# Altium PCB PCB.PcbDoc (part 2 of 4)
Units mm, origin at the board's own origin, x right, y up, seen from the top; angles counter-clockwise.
Board outline 430 x 130 mm, 2 copper layers (Top Layer, Bottom Layer); 471 components, 267 nets, 1806 pads, 471 vias.
Unrouted connection lines stored in the file: 127.
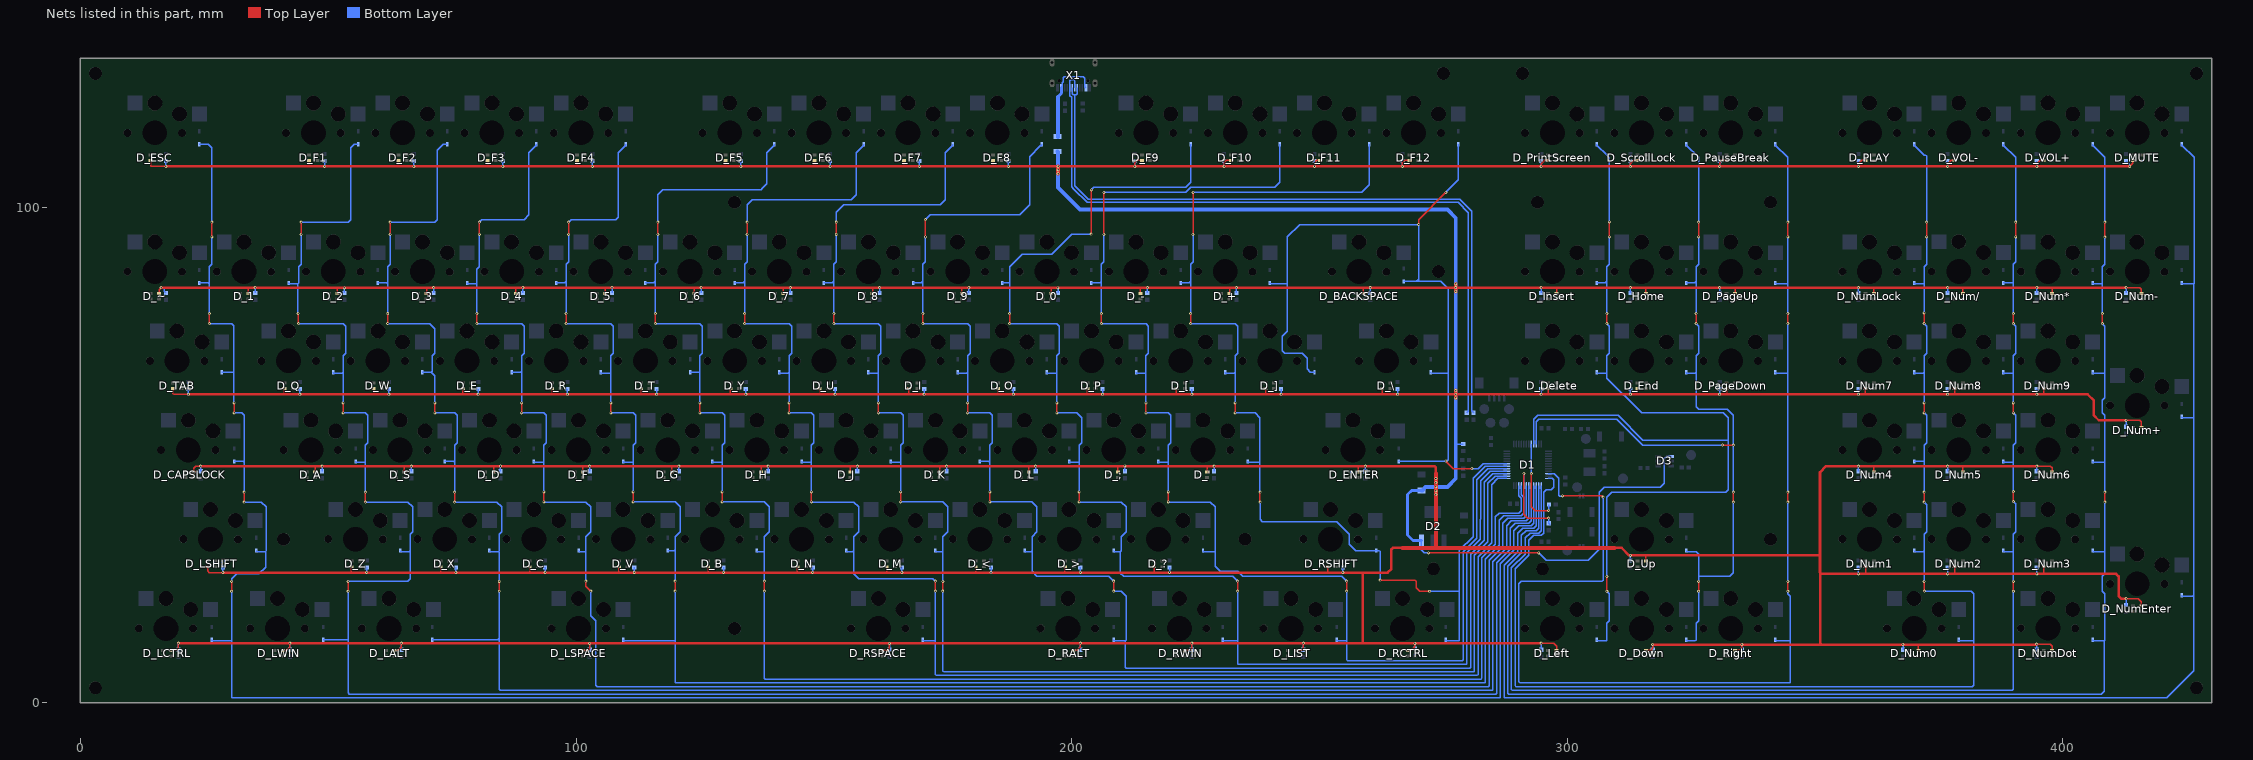
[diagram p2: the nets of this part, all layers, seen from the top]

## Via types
v1: diameter 0.6, hole 0.3, Top Layer to Bottom Layer, tented both sides, 471 vias

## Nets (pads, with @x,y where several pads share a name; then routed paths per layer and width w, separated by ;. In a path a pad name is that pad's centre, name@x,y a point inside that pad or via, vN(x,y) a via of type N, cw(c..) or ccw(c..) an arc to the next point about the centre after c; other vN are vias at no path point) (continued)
+5: C7.1 C9.2 C10.2 C11.2 C12.2 C13.2 C14.2 C15.2 C16.2 C17.2 C18.2 C19.2 C20.2 C21.2 C22.2 C23.2 C24.2 C25.2 C26.2 C27.2 C28.2 C29.2 C30.2 C31.2 C32.2 C33.2 C34.2 C35.2 C36.2 C37.2 C38.2 C39.2 C40.2 C41.2 C42.2 C43.2 C44.2 C45.2 C46.2 C47.2 C48.2 C49.2 C50.2 C51.2 C52.2 C53.2 C54.2 C55.2 C56.2 C57.2 C58.2 C59.2 C60.2 C61.2 C62.2 C63.2 C64.2 C65.2 C66.2 C67.2 C68.2 C69.2 C70.2 C71.2 C72.2 C73.2 C74.2 C75.2 C76.2 C77.2 C78.2 C79.2 C80.2 C81.2 C82.2 C83.2 C84.2 C85.2 C86.2 C87.2 C88.2 C89.2 C90.2 C91.2 C92.2 C93.2 C94.2 C95.2 C96.2 C97.2 C98.2 C99.2 C100.2 C101.2 C102.2 C103.2 C104.2 C105.2 C106.2 C107.2 C108.2 C109.2 C110.2 C111.2 C112.2 C113.2 C114.2 C115.2 C116.2 C117.2 D2.3 D3.1 D_0.4 D_1.4 D_2.4 D_3.4 D_4.4 D_5.4 D_6.4 D_7.4 D_8.4 D_9.4 D_'.4 D_+.4 D_-.4 D_;.4 D_<.4 D_>.4 D_?.4 D_[.4 D_\.4 D_].4 D_A.4 D_B.4 D_BACKSPACE.4 D_C.4 D_CAPSLOCK.4 D_D.4 D_Delete.4 D_Down.4 D_E.4 D_End.4 D_ENTER.4 D_ESC.4 D_F1.4 D_F2.4 D_F3.4 D_F4.4 D_F5.4 D_F6.4 D_F7.4 D_F8.4 D_F9.4 D_F10.4 D_F11.4 D_F12.4 D_F.4 D_G.4 D_H.4 D_Home.4 D_I.4 D_Insert.4 D_J.4 D_K.4 D_L.4 D_LALT.4 D_LCTRL.4 D_Left.4 D_LIST.4 D_LSHIFT.4 D_LSPACE.4 D_LWIN.4 D_M.4 D_MUTE.4 D_N.4 D_Num0.4 D_Num1.4 D_Num2.4 D_Num3.4 D_Num4.4 D_Num5.4 D_Num6.4 D_Num7.4 D_Num8.4 D_Num9.4 D_Num*.4 D_Num+.4 D_Num-.4 D_Num/.4 D_NumDot.4 D_NumEnter.4 D_NumLock.4 D_O.4 D_P.4 D_PageDown.4 D_PageUp.4 D_PauseBreak.4 D_PLAY.4 D_PrintScreen.4 D_Q.4 D_R.4 D_RALT.4 D_RCTRL.4 D_Right.4 D_RSHIFT.4 D_RSPACE.4 D_RWIN.4 D_S.4 D_ScrollLock.4 D_T.4 D_TAB.4 D_U.4 D_Up.4 D_V.4 D_VOL+.4 D_VOL-.4 D_W.4 D_X.4 D_Y.4 D_Z.4 D_~.4 F1.2 R14.2 | length 2845
  Top Layer w0.254: D_ESC.4@14.15,109.44 14.15,108.399 14.299,108.25 v1(17.25,108.25) ; D_~.4@15.85,82.56 15.85,83.35 v1(16.25,83.75) ; D_LCTRL.4@18.35,10.56 19.31,10.56 19.75,11 v1@19.75,12 ; D_TAB.4@18.65,63.44 18.65,62.399 18.799,62.25 v1(21.75,62.25) ; D_CAPSLOCK.4@23.123,46.733 22.95,46.56 D_CAPSLOCK.4@22.85,46.56 22.85,47.35 23.25,47.75 v1@24.219,47.75 ; D_LSHIFT.4@25.65,27.44 25.65,26.6 26,26.25 v1@28.75,26.25 ; D_1.4@33.85,82.56 33.85,83.6 34,83.75 ; D_LWIN.4@40.85,10.56 41.56,10.56 42.241,11.241 v1@42.241,12 ; 41,62.25 41.15,62.4 D_Q.4@41.15,63.44 ; D_F1.4@46.15,109.44 46.15,108.35 46.25,108.25 ; 47.25,47.75 47.35,47.65 D_A.4@47.35,46.56 ; D_2.4@51.85,82.56 51.85,83.6 52,83.75 ; 54.5,26.25 54.65,26.4 D_Z.4@54.65,27.44 ; D_W.4@59.15,63.44 59.15,62.35 59.25,62.25 ; D_LALT.4@63.35,10.56 64.06,10.56 64.741,11.241 v1@64.741,12 ; 64,108.25 64.15,108.4 D_F2.4@64.15,109.44 ; 65.25,47.75 65.35,47.65 D_S.4@65.35,46.56 ; D_3.4@69.85,82.56 69.85,83.6 70,83.75 ; D_X.4@72.65,27.44 72.65,26.35 72.75,26.25 ; D_E.4@77.15,63.44 77.15,62.35 77.25,62.25 ; 82.125,108.25 82.15,108.275 D_F3.4@82.15,109.44 ; D_D.4@83.35,46.56 83.35,47.6 83.5,47.75 ; D_4.4@87.85,82.56 87.85,83.6 88,83.75 ; 90.5,26.25 90.65,26.4 D_C.4@90.65,27.44 ; D_R.4@95.15,63.44 95.15,62.35 95.25,62.25 ; D_F4.4@100.15,109.44 100.15,108.35 100.25,108.25 ; D_LSPACE.4@101.35,10.56 102.31,10.56 102.75,11 102.75,11.75 102.853,11.853 v1@103,12 ; D_F.4@101.35,46.56 101.35,47.6 101.5,47.75 ; 105.75,83.75 105.85,83.65 D_5.4@105.85,82.56 ; 108.5,26.25 108.65,26.4 D_V.4@108.65,27.44 ; D_T.4@113.15,63.44 113.15,62.35 113.25,62.25 ; D_G.4@119.35,46.56 119.35,47.6 119.5,47.75 ; 123.75,83.75 123.85,83.65 D_6.4@123.85,82.56 ; D_B.4@126.65,27.44 126.65,26.35 126.75,26.25 ; D_F5.4@130.15,109.44 130.15,108.35 130.25,108.25 ; 131,62.25 131.15,62.4 D_Y.4@131.15,63.44 ; 137.25,47.75 137.35,47.65 D_H.4@137.35,46.56 ; D_7.4@141.85,82.56 141.85,83.6 142,83.75 ; D_N.4@144.65,27.44 144.65,26.35 144.75,26.25 ; D_F6.4@148.15,109.44 148.15,108.65 148.105,108.605 148.105,108.395 148.25,108.25 ; 149,62.25 149.15,62.4 D_U.4@149.15,63.44 ; D_J.4@155.35,46.56 155.35,47.6 155.5,47.75 ; 159.75,83.75 159.85,83.65 D_8.4@159.85,82.56 ; D_RSPACE.4@161.85,10.56 162.81,10.56 163.219,10.969 v1(163.219,11.988) v1@163.219,12 ; D_M.4@162.65,27.44 162.65,26.35 162.75,26.25 ; 166,108.25 166.15,108.4 D_F7.4@166.15,109.44 ; D_I.4@167.15,63.44 167.15,62.35 167.25,62.25 ; D_K.4@173.35,46.56 173.35,47.6 173.5,47.75 ; D_9.4@177.85,82.56 177.85,83.6 178,83.75 ; 180.5,26.25 180.65,26.4 D_<.4@180.65,27.44 ; 184,108.25 184.15,108.4 D_F8.4@184.15,109.44 ; 185,62.25 185.15,62.4 D_O.4@185.15,63.44 ; 191.25,47.75 191.35,47.65 D_L.4@191.35,46.56 ; D_0.4@195.85,82.56 195.85,83.6 196,83.75 ; D_>.4@198.65,27.44 198.65,26.35 198.75,26.25 ; D_RALT.4@200.35,10.56 201.06,10.56 201.741,11.241 v1@201.741,12 ; D_P.4@203.15,63.44 203.15,62.35 203.25,62.25 ; 209.25,47.75 209.35,47.65 209.35,46.56 ; v1(212.75,108.25) 212.75,109 213.19,109.44 D_F9.4@214.15,109.44 ; 213.75,83.75 213.85,83.65 D_-.4@213.85,82.56 ; D_?.4@216.65,27.44 216.65,26.35 216.75,26.25 ; D_[.4@221.15,63.44 221.15,62.35 221.25,62.25 ; D_RWIN.4@222.85,10.56 223.81,10.56 224.241,10.991 v1@224.241,12 ; D_'.4@227.35,46.56 227.35,47.6 227.5,47.75 ; v1(230.75,108.25) 230.75,109 231.19,109.44 D_F10.4@232.15,109.44 ; D_+.4@231.85,82.56 231.85,83.6 232,83.75 ; D_].4@239.15,63.44 239.15,62.35 239.25,62.25 ; D_LIST.4@245.35,10.56 246.31,10.56 246.741,10.991 v1@246.741,12 ; v1(249,108.25) 249,109 249.44,109.44 D_F11.4@250.15,109.44 ; D_RSHIFT.4@251.65,27.44 251.65,26.35 251.75,26.25 ; D_ENTER.4@257.85,46.56 257.85,47.6 258,47.75 ; D_BACKSPACE.4@258.85,82.56 258.85,83.6 259,83.75 ; 262.5,62.25 262.65,62.4 D_\.4@262.65,63.44 ; v1(266.75,108.25) 266.75,109 267.19,109.44 D_F12.4@268.15,109.44 ; D_RCTRL.4@267.85,10.56 268.56,10.56 269.25,11.25 269.25,11.996 v1@269.254,12 ; v1(272,30.25) v1(294.25,30.25) ; v1@294.75,12 297.25,12 297.85,11.4 D_Left.4@297.85,10.56 ; v1(294.75,108.25) 294.75,108.75 295.44,109.44 D_PrintScreen.4@296.15,109.44 ; D_Delete.4@296.15,63.44 296.15,62.35 296.25,62.25 ; D_Insert.4@297.85,82.56 297.85,83.6 298,83.75 ; v1@312.75,108.25 312.75,108.75 313.44,109.44 D_ScrollLock.4@314.15,109.44 ; 314,62.25 314.15,62.4 D_End.4@314.15,63.44 ; 315.75,83.75 315.85,83.65 D_Home.4@315.85,82.56 ; D_Down.4@315.85,10.56 316.81,10.56 317.25,11 v1@317.25,11.75 ; D_Up.4@315.85,28.56 315.85,29.6 316,29.75 ; v1(330.75,108.25) 330.75,109 331.19,109.44 D_PauseBreak.4@332.15,109.44 ; 332,62.25 332.15,62.4 D_PageDown.4@332.15,63.44 ; D_Right.4@333.85,10.56 334.81,10.56 335.241,10.991 v1@335.241,11.75 ; D_PageUp.4@333.85,82.56 333.85,83.6 334,83.75 ; v1(358.75,108.25) 358.75,108.75 359.44,109.44 D_PLAY.4@360.15,109.44 ; D_Num1.4@360.15,27.44 360.25,27.34 360.25,26 ; D_Num7.4@360.15,63.44 360.15,62.35 360.25,62.25 ; D_Num4.4@361.85,46.56 361.85,47.6 362,47.75 ; D_NumLock.4@361.85,82.56 361.85,83.6 362,83.75 ; 370.75,11.75 370.85,11.65 D_Num0.4@370.85,10.56 ; v1(376.75,108.25) 376.75,108.75 377.44,109.44 D_VOL-.4@378.15,109.44 ; D_Num2.4@378.15,27.44 378.15,26.1 378.25,26 ; D_Num8.4@378.15,63.44 378.15,62.35 378.25,62.25 ; 379.75,47.75 379.85,47.65 D_Num5.4@379.85,46.56 ; 379.75,83.75 379.85,83.65 D_Num/.4@379.85,82.56 ; v1@394.75,11.75 394.832,11.832 397.418,11.832 397.85,11.4 D_NumDot.4@397.85,10.56 ; v1@394.75,47.75 397.5,47.75 397.85,47.4 D_Num6.4@397.85,46.56 ; v1(394.75,108.25) 394.75,108.75 395.44,109.44 D_VOL+.4@396.15,109.44 ; D_Num3.4@396.15,27.44 396.15,26.1 396.25,26 ; D_Num9.4@396.15,63.44 396.15,62.35 396.25,62.25 ; D_Num*.4@397.85,82.56 397.85,83.6 398,83.75 ; v1@412.75,21 415.25,21 415.85,20.4 D_NumEnter.4@415.85,19.56 ; v1(412.75,57) 415.5,57 415.85,56.65 D_Num+.4@415.85,55.56 ; v1(412.75,83.75) 415.5,83.75 415.85,83.4 D_Num-.4@415.85,82.56 ; v1(413.5,108.25) 414.15,108.9 D_MUTE.4@414.15,109.44
  Top Layer w0.508: v1(16.25,83.75) 34,83.75 v1(35.25,83.75) 52,83.75 70,83.75 v1(71.25,83.75) 88,83.75 v1(89.25,83.75) 105.75,83.75 v1(107.25,83.75) 123.75,83.75 v1(125.25,83.75) 142,83.75 v1(143.25,83.75) 159.75,83.75 v1(161.25,83.75) 178,83.75 v1(179.25,83.75) 196,83.75 213.75,83.75 232,83.75 v1(233.25,83.75) 259,83.75 v1(260.25,83.75) v1(277.5,83.75) v1(294.75,83.75) 298,83.75 v1(312.75,83.75) 315.75,83.75 v1(330.75,83.75) 334,83.75 v1(358.75,83.75) 362,83.75 v1(376.75,83.75) 379.75,83.75 v1(394.75,83.75) 398,83.75 v1(412.75,83.75) ; v1(17.25,108.25) 46.25,108.25 v1(49.25,108.25) 64,108.25 v1(67.25,108.25) 82.125,108.25 v1(85.25,108.25) 100.25,108.25 v1(103.277,108.25) 130.25,108.25 v1(133.25,108.25) 148.25,108.25 v1(151.25,108.25) 166,108.25 v1(169.25,108.25) 184,108.25 v1(187.25,108.25) v1(197.25,108.25) v1(212.75,108.25) v1(230.75,108.25) v1(249,108.25) v1(266.75,108.25) v1(294.75,108.25) 312.75,108.25 v1(330.75,108.25) v1(358.75,108.25) v1(376.75,108.25) v1(394.75,108.25) v1(413.5,108.25) ; v1@19.75,12 42.241,12 64.741,12 v1@102.721,12 ; v1(21.75,62.25) 41,62.25 v1(44.25,62.25) 59.25,62.25 v1(62.25,62.25) 77.25,62.25 v1(80.25,62.25) 95.25,62.25 v1(98.25,62.25) 113.25,62.25 v1(116.25,62.25) 131,62.25 v1(134.25,62.25) 149,62.25 167.25,62.25 v1(170.25,62.25) 185,62.25 v1(188.25,62.25) 203.25,62.25 v1(206.25,62.25) 221.25,62.25 v1(224.25,62.25) 239.25,62.25 v1(242.25,62.25) 262.5,62.25 v1(265.75,62.25) v1(277.5,62.25) v1(294.75,62.25) 296.25,62.25 v1(312.75,62.25) 314,62.25 v1(330.75,62.25) 332,62.25 v1(358.75,62.25) 360.25,62.25 v1(376.75,62.25) 378.25,62.25 v1(394.75,62.25) 396.25,62.25 405,62.25 406.25,61 406.25,58 407.25,57 v1(412.75,57) ; v1@24.219,47.75 v1(24.25,47.75) 47.25,47.75 v1(48.75,47.75) 65.25,47.75 v1(66.75,47.75) 83.5,47.75 v1(84.75,47.75) 101.5,47.75 v1(102.75,47.75) 119.5,47.75 120.747,47.75 137.25,47.75 138.747,47.75 155.5,47.75 156.747,47.75 173.5,47.75 v1(174.75,47.75) 191.25,47.75 192.747,47.75 209.25,47.75 210.748,47.75 227.5,47.75 228.747,47.75 258,47.75 259.247,47.75 273.202,47.75 273.5,47.452 273.5,46.25 ; v1@28.75,26.25 54.5,26.25 57.741,26.25 72.75,26.25 75.741,26.25 90.5,26.25 93.741,26.25 108.5,26.25 111.741,26.25 126.75,26.25 129.741,26.25 144.75,26.25 147.741,26.25 162.75,26.25 165.741,26.25 180.5,26.25 183.724,26.25 198.75,26.25 201.741,26.25 216.75,26.25 219.741,26.25 251.75,26.25 254.741,26.25 258.75,26.25 ; v1@103,12 163.219,12 201.741,12 224.241,12 246.741,12 258.75,12 ; 266.75,31.25 264.798,31.25 264.5,30.952 264.5,27 263.75,26.25 258.75,26.25 ; v1@294.75,12 269.254,12 258.75,12 ; 309.5,31.25 311,31.25 312.5,29.75 312.747,29.75 316,29.75 351,29.75 ; v1@317.25,11.75 335.241,11.75 351.345,11.75 ; 351.149,26.149 351,26.298 351,29.75 ; v1@394.75,11.75 370.75,11.75 367.737,11.75 351.345,11.75 ; v1@394.75,47.75 379.75,47.75 376.766,47.75 362,47.75 358.745,47.75 352.25,47.75 351,46.5 351,29.75 ; v1@412.75,21 411.75,21 411.25,21.5 411.25,25.5 410.75,26 396.25,26 394.747,26 378.25,26 376.747,26 360.25,26 358.747,26 351.048,26 351.048,12.048 351.345,11.75 ; 258.75,12 258.75,26.25
  Top Layer w0.8: v1(197.25,106.75) v1(197.25,108.25) ; 266.75,31.25 273.5,31.25 ; 273.5,46.25 v1(273.5,45.25) v1(273.5,44.4) v1(273.5,43.575) v1(273.5,42.75) v1(273.5,42) 273.5,31.25 ; v1(277.5,61.5) v1(277.5,62.25) v1(277.5,63) ; v1(277.5,83) v1(277.5,83.75) v1(277.5,84.5) ; 309.5,31.25 273.5,31.25
  Bottom Layer w0.254: v1(16.25,83.75) 16.75,83.75 16.952,83.548 16.952,82.998 C93.2@17.25,82.7 ; v1(17.25,108.25) C109.2@17.25,109.3 ; C30.2@19.75,10.7 v1@19.75,12 ; v1(21.75,62.25) C108.2@21.75,63.3 ; C62.2@24.25,46.7 v1(24.25,47.75) ; v1(28.741,26.286) 28.741,27.291 C31.2@28.75,27.3 ; C94.2@35.25,82.7 v1(35.25,83.75) ; C33.2@42.25,10.7 v1@42.25,12 ; v1(44.25,62.25) C69.2@44.25,63.3 ; C63.2@48.75,46.7 v1(48.75,47.75) ; v1(49.25,108.25) C110.2@49.25,109.3 ; C95.2@53.25,82.7 v1@53.25,83.75 ; v1@57.75,26.25 C32.2@57.75,27.3 ; v1(62.25,62.25) C64.2@62.25,63.3 ; C34.2@64.75,10.7 v1@64.75,12 ; C65.2@66.75,46.7 v1(66.75,47.75) ; v1(67.25,108.25) C111.2@67.25,109.3 ; C61.2@71.25,82.7 v1(71.25,83.75) ; v1@75.75,26.25 C36.2@75.75,27.3 ; v1(80.25,62.25) C67.2@80.25,63.3 ; C66.2@84.75,46.7 v1(84.75,47.75) ; v1(85.25,108.25) C112.2@85.25,109.3 ; C96.2@89.25,82.7 v1(89.25,83.75) ; v1@93.75,26.25 C37.2@93.75,27.3 ; v1(98.25,62.25) C68.2@98.25,63.3 ; C35.2@102.75,10.7 v1@102.75,11.985 ; C29.2@102.75,46.7 v1(102.75,47.75) ; C113.2@103.25,109.3 103.25,108.277 v1(103.277,108.25) ; C97.2@107.25,82.7 v1(107.25,83.75) ; v1@111.75,26.25 C38.2@111.75,27.3 ; v1(116.25,62.25) C42.2@116.25,63.3 ; C41.2@120.75,46.7 v1@120.75,47.75 ; C100.2@125.25,82.7 v1(125.25,83.75) ; v1@129.75,26.25 C39.2@129.75,27.3 ; v1(133.25,108.25) C114.2@133.25,109.3 ; v1(134.25,62.25) C43.2@134.25,63.3 ; C44.2@138.75,46.7 v1@138.75,47.75 ; C101.2@143.25,82.7 v1(143.25,83.75) ; v1@147.75,26.25 C40.2@147.75,27.3 ; v1(151.25,108.25) C115.2@151.25,109.3 ; v1@152.25,62.25 C46.2@152.25,63.3 ; C70.2@156.75,46.7 v1@156.75,47.75 ; C102.2@161.25,82.7 v1(161.25,83.75) ; C47.2@163.25,10.7 v1@163.25,11.988 ; v1@165.75,26.25 C45.2@165.75,27.3 ; v1(169.25,108.25) C116.2@169.25,109.3 ; v1(170.25,62.25) C71.2@170.25,63.3 ; C72.2@174.75,46.7 v1(174.75,47.75) ; C103.2@179.25,82.7 v1(179.25,83.75) ; v1@183.75,26.25 C75.2@183.75,27.3 ; v1(187.25,108.25) C117.2@187.25,109.3 ; v1(188.25,62.25) C73.2@188.25,63.3 ; C74.2@192.75,46.7 v1@192.75,47.75 ; C104.2@197.25,82.7 v1@197.25,83.75 ; v1(201.741,26.286) 201.741,27.291 C77.2@201.75,27.3 ; C76.2@201.75,10.7 v1@201.75,12 ; v1(206.25,62.25) C48.2@206.25,63.3 ; C10.2@210.75,46.7 v1@210.75,47.75 ; v1(212.75,108.25) C89.2@212.75,109.3 ; C105.2@215.25,82.7 v1@215.25,83.75 ; v1@219.75,26.25 C13.2@219.75,27.3 ; C14.2@224.25,10.7 v1@224.25,12 ; v1(224.25,62.25) C98.2@224.25,63.3 ; C12.2@228.75,46.7 v1@228.75,47.75 ; v1(230.75,108.25) C90.2@230.75,109.3 ; C106.2@233.25,82.7 v1(233.25,83.75) ; v1(242.25,62.25) C99.2@242.25,63.3 ; C78.2@246.75,10.7 v1@246.75,12 ; v1(249,108.25) C91.2@249,109.3 ; v1@254.75,26.25 C80.2@254.75,27.3 ; C9.2@259.25,46.7 v1@259.25,47.75 ; C107.2@260.25,82.7 v1(260.25,83.75) ; v1(265.75,62.25) C60.2@265.75,63.3 ; v1(266.75,108.25) C92.2@266.75,109.3 ; C79.2@269.25,10.95 v1@269.25,12 ; D2.3@270.575,32.725 270.575,30.845 271.17,30.25 v1(272,30.25) ; v1@273.5,43.55 v1(273.5,43.575) ; 277.5,52 277.7,52.2 R14.2@279,52.2 ; v1(294.25,30.25) 295.75,28.75 304.25,28.75 306.5,31 306.5,42.5 307.5,43.5 318.75,43.5 319.589,44.339 319.589,49.237 320.051,49.698 D3.1@320.946,49.698 ; C83.2@294.75,10.7 v1@294.75,12 ; v1(294.75,62.25) C87.2@294.75,63.3 ; C82.2@294.75,82.7 v1(294.75,83.75) ; v1(294.75,108.25) C11.2@294.75,109.3 ; v1(312.727,108.188) 312.727,109.277 C81.2@312.75,109.3 ; C86.2@312.75,28.7 v1@312.75,29.75 ; v1(312.75,62.25) C88.2@312.75,63.3 ; C15.2@312.75,82.7 v1(312.75,83.75) ; C84.2@317.25,10.7 v1@317.25,11.75 ; v1(330.75,62.25) C49.2@330.75,63.3 ; C18.2@330.75,82.7 v1(330.75,83.75) ; v1(330.75,108.25) C16.2@330.75,109.3 ; C85.2@335.25,10.7 v1@335.25,11.75 ; v1@358.75,26 C55.2@358.75,27.3 ; C26.2@358.75,46.7 v1@358.75,47.75 ; v1(358.75,62.25) C23.2@358.75,63.3 ; C19.2@358.75,82.7 v1(358.75,83.75) ; v1(358.75,108.25) C50.2@358.75,109.3 ; C17.2@367.75,10.7 v1@367.75,11.75 ; v1@376.75,26 C56.2@376.75,27.3 ; C27.2@376.75,46.7 v1@376.75,47.75 ; v1(376.75,62.25) C24.2@376.75,63.3 ; C20.2@376.75,82.7 v1(376.75,83.75) ; v1(376.75,108.25) C51.2@376.75,109.3 ; v1(394.747,47.744) 394.747,46.703 C28.2@394.75,46.7 ; C58.2@394.75,10.7 v1@394.75,11.75 ; v1@394.75,26 C57.2@394.75,27.3 ; v1(394.75,62.25) C25.2@394.75,63.3 ; C21.2@394.75,82.7 v1(394.75,83.75) ; v1(394.75,108.25) C52.2@394.75,109.3 ; v1(412.747,20.994) 412.747,19.703 C59.2@412.75,19.7 ; C54.2@412.75,55.7 v1(412.75,57) ; C22.2@412.75,82.7 v1(412.75,83.75) ; C53.2@412.75,109.3 413.434,108.616 413.434,108.316 v1(413.5,108.25)
  Bottom Layer w0.6: C7.1@270.55,42.85 268.625,42.85 267.775,42 267.775,33.85 268.9,32.725 D2.3@270.575,32.725
  Bottom Layer w0.8: F1.2@197.1,111.25 197.25,111.1 v1(197.25,106.75) 197.25,103.975 201.725,99.5 275.825,99.5 277.5,97.825 v1(277.5,84.5) v1(277.5,83.75) v1(277.5,83) v1(277.5,63) v1(277.5,62.25) v1(277.5,61.5) 277.5,52 277.5,45.225 275.825,43.55 v1@273.5,43.55 ; C7.1@270.55,42.85 270.75,42.85 270.95,43.05 270.95,43.081 271.419,43.55 v1@273.5,43.55 ; v1(273.5,42) v1(273.5,42.75) v1@273.5,43.55 ; v1(273.5,45.25) v1(273.5,44.4) v1@273.5,43.55
  other v1: 317.241,11.786 335.241,11.786 367.737,11.793 394.713,11.832 102.721,11.985 269.254,11.973 19.741,12.036 42.241,12.036 64.741,12.036 201.741,12.036 224.241,12.036 246.741,12.036 294.729,12.048 358.747,25.994 376.747,25.994 394.747,25.994 183.724,26.247 57.741,26.286 75.741,26.286 93.741,26.286 111.741,26.286 129.741,26.286 147.741,26.286 165.741,26.286 219.741,26.286 254.741,26.286 312.747,29.744 120.747,47.744 138.747,47.744 156.747,47.744 192.747,47.744 228.747,47.744 259.247,47.744 358.745,47.742 376.766,47.765 210.748,47.782 152.285,62.251 53.26,83.723 197.22,83.73 215.264,83.742 197.25,107.5
+5_usb: F1.1 X1.VCC1 X1.VCC2 | length 19.2
  Bottom Layer w0.254: F1.1@197.1,114.25 F1.1@197.3,114.45 ; X1.VCC1@197.95,124.1 198.123,124.273 198.123,125.123 198.3,125.3 198.3,126.1 198.5,126.3 202.35,126.3 202.6,126.05 202.6,125.2 202.677,125.123 202.677,124.273 X1.VCC2@202.85,124.1
  Bottom Layer w0.6: 197.2,122.25 197.95,123 X1.VCC1@197.95,124.1
  Bottom Layer w0.8: F1.1@197.2,114.15 197.2,122.25
BOOT0: D1.44 R8.1 | length 17.7
  Top Layer w0.254: v1(292.75,46.25) 292.75,39.5 293.5,38.75 v1@296.25,38.75
  Bottom Layer w0.254: v1(292.75,46.25) D1.44@292.75,52.2 ; v1(296.25,38.833) 296.25,39.95 R8.1@296.3,40
BOOT1: D1.20 R9.1 | length 17.5
  Top Layer w0.254: v1(291.25,46.25) 291.25,38 292,37.25 v1(296.25,37.25)
  Bottom Layer w0.254: D1.20@291.25,43.8 v1(291.25,46.25) ; v1(296.25,37.25) R9.1@296.25,36.2 R9.1@296.548,35.902
Col_1: D1.16 VD_1.2 VD_14.2 VD_28.2 VD_42.2 VD_55.2 VD_67.2 | length 445.6
  Top Layer w0.254: v1(26,76.5) v1(26,78.5) ; v1(26.5,94) v1(26.5,97) ; v1(30.5,22.5) v1(30.5,24.5) ; v1(31,58.5) v1(31,60.5) ; v1(33,40.5) v1(33,42.5)
  Bottom Layer w0.254: VD_14.2@24,84.7 25.8,84.7 26,84.5 ; VD_1.2@24,112.7 25.8,112.7 26.5,112 v1(26.5,97) ; v1(26,76.5) 30.5,76.5 30.949,76.051 30.949,66.551 ; v1(26,78.5) 26,84.5 ; VD_67.2@26.5,12.7 26.5,12.623 26.623,12.5 30.351,12.5 30.5,12.649 ; v1(26.5,94) 26.5,88.5 26,88 26,84.5 ; VD_28.2@28.5,66.7 30.8,66.7 30.949,66.551 ; v1(30.5,22.5) 30.5,12.649 ; v1(30.5,24.5) 30.5,25 31.5,26 36,26 37.351,27.351 37.351,30.5 ; VD_42.2@31,48.7 32.8,48.7 33,48.5 ; v1(31,58.5) 32.5,58.5 33,58 33,48.5 ; v1(31,60.5) 30.949,60.551 30.949,66.551 ; v1(33,40.5) 36.5,40.5 37.5,39.5 37.5,30.649 37.351,30.5 ; v1(33,42.5) 33,48.5 ; VD_55.2@35.5,30.7 35.5,30.623 35.623,30.5 37.351,30.5 ; D1.16@293.25,43.8 293.25,36.25 292.75,35.75 290.25,35.75 289.25,34.75 289.25,30.75 286.5,28 286.5,1.149 286.351,1 30.649,1 30.5,1.149 30.5,12.649
Col_2: D1.17 VD_2.2 VD_15.2 VD_29.2 VD_43.2 VD_56.2 VD_68.2 | length 449.4
  Top Layer w0.254: v1(43.926,78.574) 43.926,76.574 v1(44,76.5) ; v1(44.5,94.5) v1(44.5,97) ; v1(53,58.5) v1(53,60.5) ; v1(54,22.5) v1(54,24.5) ; v1(57.5,40.5) v1(57.5,42.5)
  Bottom Layer w0.254: VD_15.2@42,84.7 42,84.623 42.123,84.5 43.851,84.5 ; v1(43.926,78.574) 43.851,78.649 43.851,84.5 ; v1(44,76.5) 53,76.5 53.5,76 53.5,70.5 53,70 53,66.649 ; v1(44.5,94.5) 44.5,88.5 44,88 44,84.649 43.851,84.5 ; v1(44.5,97) 54,97 54.5,97.5 54.5,112 55.2,112.7 VD_2.2@56,112.7 ; VD_68.2@49,12.7 53.851,12.7 54,12.849 ; VD_29.2@51,66.7 51,66.623 51.123,66.5 52.851,66.5 53,66.649 ; v1(53,58.5) 57.5,58.5 58,58 58,52.5 57.5,52 57.5,48.649 ; v1(53,60.5) 53,66.649 ; v1(54,22.5) 54,12.849 ; v1(54,24.5) 66,24.5 66.5,25 66.5,30.649 ; VD_43.2@55.5,48.7 55.5,48.623 55.623,48.5 57.351,48.5 57.5,48.649 ; v1(57.5,40.5) 66,40.5 67,39.5 67,34.5 66.5,34 66.5,30.649 ; v1(57.5,42.5) 57.5,48.649 ; VD_56.2@64.5,30.7 64.5,30.623 64.623,30.5 66.351,30.5 66.5,30.649 ; D1.17@292.75,43.8 292.75,36.75 292.25,36.25 289.5,36.25 288.5,35.25 288.5,31 285.75,28.25 285.75,1.899 285.601,1.75 54.25,1.75 54,2 54,12.849
Col_3: D1.18 VD_3.2 VD_16.2 VD_30.2 VD_44.2 VD_57.2 VD_69.2 | length 411.9
  Top Layer w0.254: v1@62,76.5 v1(62,78.5) ; v1(62.5,94.5) v1(62.5,97) ; v1(71.5,58.5) v1(71.5,60.5) ; v1(75.5,40.5) v1(75.5,42.5) ; v1(84.5,22.5) v1(84.5,24.5)
  Bottom Layer w0.254: VD_16.2@60,84.7 61.8,84.7 62,84.5 ; v1(61.987,76.524) 70.476,76.524 71.5,75.5 71.5,70.5 71,70 71,66.9 70.8,66.7 ; v1(62,78.5) 62,84.5 ; v1(62.5,94.5) 62.5,88.5 62,88 62,84.5 ; v1(62.5,97) 71.5,97 72,97.5 72,111.5 73.2,112.7 VD_3.2@74,112.7 ; VD_30.2@69,66.7 70.8,66.7 ; VD_69.2@71,12.7 84.2,12.7 84.5,13 ; v1(71.5,58.5) 75.5,58.5 76,58 76,52.5 75.5,52 75.5,48.7 75.4,48.6 ; v1(71.5,60.5) 71.5,66 70.8,66.7 ; VD_44.2@73.5,48.7 75.3,48.7 75.4,48.6 ; v1(75.5,40.5) 84,40.5 85,39.5 85,34.5 84.5,34 84.5,30.649 84.351,30.5 ; v1(75.5,42.5) 75.5,48.5 75.4,48.6 ; VD_57.2@82.5,30.7 82.5,30.623 82.623,30.5 84.351,30.5 ; v1(84.5,22.5) 84.5,13 ; v1(84.5,24.5) 84.5,30.351 84.351,30.5 ; D1.18@292.25,43.8 292.25,37.25 291.75,36.75 288.75,36.75 287.75,35.75 287.75,31.25 285,28.5 285,2.649 284.851,2.5 84.75,2.5 84.5,2.75 84.5,13
Col_4: D1.19 VD_4.2 VD_17.2 VD_31.2 VD_45.2 VD_58.2 | length 377.7
  Top Layer w0.254: v1(80,76.5) v1(80,78.5) ; v1(80.5,94.5) v1(80.5,97) ; v1(89,58.5) v1(89,60.5) ; v1(93.491,42.536) 93.5,42.527 v1@93.5,40.5 ; v1(101.991,24.536) 101.991,23.509 v1@103,22.5
  Bottom Layer w0.254: VD_17.2@78,84.7 78,84.623 78.123,84.5 79.851,84.5 80,84.649 ; v1(80,76.5) 89,76.5 89.5,76 89.5,70.5 89,70 89,66.849 ; v1(80,78.5) 80,84.649 ; v1(80.5,94.5) 80.5,88 80,87.5 80,84.649 ; v1(80.5,97) 81,97.5 89.5,97.5 90.5,98.5 90.5,111.025 92,112.525 VD_4.2@92,112.7 ; VD_31.2@87,66.7 88.851,66.7 89,66.849 ; v1(89,58.5) 93.5,58.5 94,58 94,52.5 93.5,52 93.5,48.649 ; v1(89,60.5) 89,66.849 ; VD_45.2@91.5,48.7 91.5,48.623 91.623,48.5 93.351,48.5 93.5,48.649 ; v1(93.491,40.536) 93.527,40.5 102,40.5 103,39.5 103,34.5 102,33.5 102,30.649 ; v1@93.5,42.5 93.5,48.649 ; VD_58.2@100.5,30.7 100.5,30.623 100.623,30.5 101.851,30.5 102,30.649 ; v1@102,24.5 102,30.649 ; v1(102.991,22.536) 102.991,17.509 104,16.5 104,3.5 104.25,3.25 284.101,3.25 284.25,3.399 284.25,28.75 287,31.5 287,36.25 288,37.25 291.25,37.25 291.75,37.75 D1.19@291.75,43.8
Col_5: D1.21 VD_5.2 VD_18.2 VD_32.2 VD_46.2 VD_59.2 VD_70.2 | length 370.1
  Top Layer w0.254: v1(98,76.5) v1(98,78.5) ; v1(98.5,94.5) v1(98.5,97) ; v1(107,58.5) v1(107,60.5) ; v1(111.491,42.536) 111.5,42.527 v1@111.5,40.5 ; v1(119.991,24.536) 120,24.527 v1@120,22.5
  Bottom Layer w0.254: VD_18.2@96,84.7 97.7,84.7 98,85 ; v1(98,76.5) 107,76.5 107.5,76 107.5,70.5 107,70 107,66.649 ; v1(98,78.5) 98,85 ; v1(98.5,94.5) 98.5,89 98,88.5 98,85 ; v1(98.5,97) 99,97.5 108,97.5 108.5,98 108.5,111.025 110,112.525 VD_5.2@110,112.7 ; VD_32.2@105,66.7 105,66.623 105.123,66.5 106.851,66.5 107,66.649 ; v1(107,58.5) 111.5,58.5 112,58 112,52.5 111.5,52 111.5,48.649 ; v1(107,60.5) 107,66.649 ; VD_70.2@109.5,12.7 109.5,12.623 109.623,12.5 119.842,12.5 119.991,12.649 ; VD_46.2@109.5,48.7 109.5,48.623 109.623,48.5 111.351,48.5 111.5,48.649 ; v1(111.491,40.536) 119.964,40.536 121,39.5 121,34.5 120,33.5 120,30.849 ; v1@111.5,42.5 111.5,48.649 ; VD_59.2@118.5,30.7 119.851,30.7 120,30.849 ; v1(119.991,22.536) 119.991,12.649 ; v1@120,24.5 120,30.849 ; D1.21@290.75,43.8 290.75,42 291.25,41.5 291.25,38.25 290.75,37.75 287.149,37.75 286.25,36.851 286.25,31.75 283.5,29 283.5,4.149 283.351,4 120.14,4 119.991,4.149 119.991,12.649
Col_6: D1.22 VD_6.2 VD_19.2 VD_33.2 VD_47.2 VD_60.2 | length 350.9
  Top Layer w0.254: v1(116,76.5) v1(116,78.5) ; v1(116.5,94.5) v1(116.5,97) ; v1(125,58.5) v1(125,60.5) ; v1(129.491,42.536) 129.5,42.527 v1@129.5,40.5 ; v1(137.991,24.536) 138,24.527 v1@138,22.5
  Bottom Layer w0.254: VD_19.2@114,84.7 115.7,84.7 116,85 ; v1(116,76.5) 125,76.5 125.5,76 125.5,70.5 125,70 125,66.849 ; v1(116,78.5) 116,85 ; v1(116.5,94.5) 116.5,89 116,88.5 116,85 ; v1(116.5,97) 116.5,102.5 117.5,103.5 137.351,103.5 137.5,103.649 137.5,103.763 138.5,104.763 138.5,111.025 140,112.525 VD_6.2@140,112.7 ; VD_33.2@123,66.7 124.851,66.7 125,66.849 ; v1(125,58.5) 129.5,58.5 130,58 130,52.5 129.5,52 129.5,48.649 ; v1(125,60.5) 125,66.849 ; VD_47.2@127.5,48.7 127.5,48.623 127.623,48.5 129.351,48.5 129.5,48.649 ; v1(129.491,40.536) 137.964,40.536 139,39.5 139,34.5 138,33.5 138,30.649 ; v1@129.5,42.5 129.5,48.649 ; VD_60.2@136.5,30.7 136.5,30.623 136.623,30.5 137.851,30.5 138,30.649 ; v1(137.991,22.536) 137.991,4.899 138.14,4.75 282.601,4.75 282.75,4.899 282.75,29.25 285.5,32 285.5,37.5 286.25,38.25 290.25,38.25 290.75,38.75 290.75,41.25 290.25,41.75 D1.22@290.25,43.8 ; v1@138,24.5 138,30.649
Col_7: D1.25 VD_7.2 VD_20.2 VD_34.2 VD_48.2 VD_61.2 VD_71.2 | length 331.7
  Top Layer w0.254: v1(134,76.5) v1(134,78.5) ; v1(134.5,94.5) v1(134.5,97) ; v1(143,58.5) v1(143,60.5) ; v1(147.491,42.536) 147.5,42.527 v1@147.5,40.5 ; v1(172.491,24.536) 172.5,24.527 v1@172.5,22.5
  Bottom Layer w0.254: VD_20.2@132,84.7 133.7,84.7 134,85 ; v1(134,76.5) 143,76.5 143.5,76 143.5,70.5 143,70 143,66.649 ; v1(134,78.5) 134,85 ; v1(134.5,94.5) 134.5,89 134,88.5 134,85 ; v1(134.5,97) 134.5,100.5 135.5,101.5 155.5,101.5 156.5,102.5 156.5,111.025 158,112.525 VD_7.2@158,112.7 ; VD_34.2@141,66.7 141,66.623 141.123,66.5 142.851,66.5 143,66.649 ; v1(143,58.5) 147.5,58.5 148,58 148,52.5 147.5,52 147.5,48.649 ; v1(143,60.5) 143,66.649 ; VD_48.2@145.5,48.7 145.5,48.623 145.623,48.5 147.351,48.5 147.5,48.649 ; v1(147.491,40.536) 147.527,40.5 156,40.5 157,39.5 157,34.5 156,33.5 156,30.649 ; v1@147.5,42.5 147.5,48.649 ; VD_61.2@154.5,30.7 154.5,30.623 154.623,30.5 155.851,30.5 156,30.649 ; VD_71.2@170,12.7 170,12.623 170.123,12.5 172.351,12.5 172.5,12.649 ; v1(172.491,22.536) 172.5,22.527 172.5,12.649 ; v1@172.5,24.5 172,25 157,25 156,26 156,30.649 ; D1.25@287.8,45.25 286,45.25 284.75,44 284.75,38.037 284.742,38.03 284.742,32.242 282,29.5 282,5.649 281.851,5.5 172.649,5.5 172.5,5.649 172.5,12.649
Col_8: D1.26 VD_8.2 VD_21.2 VD_35.2 VD_49.2 VD_62.2 | length 310.4
  Top Layer w0.254: v1(152,76.5) v1(152,78.5) ; v1(152.5,94.5) v1(152.5,97) ; v1(161,58.5) v1(161,60.5) ; v1(165.491,42.536) 165.5,42.527 v1@165.5,40.5 ; v1@174,22.5 v1(174,24.5)
  Bottom Layer w0.254: VD_21.2@150,84.7 151.7,84.7 152,85 ; v1(152,76.5) 161,76.5 161.5,76 161.5,70.5 161,70 161,66.649 ; v1(152,78.5) 152,85 ; v1(152.5,94.5) 152.5,89 152,88.5 152,85 ; v1(152.5,97) 152.5,99 154,100.5 173.5,100.5 174.5,101.5 174.5,111.025 176,112.525 VD_8.2@176,112.7 ; VD_35.2@159,66.7 159,66.623 159.123,66.5 160.851,66.5 161,66.649 ; v1(161,58.5) 165.5,58.5 166,58 166,52.5 165.5,52 165.5,48.649 ; v1(161,60.5) 161,66.649 ; VD_49.2@163.5,48.7 163.5,48.623 163.623,48.5 165.351,48.5 165.5,48.649 ; v1(165.491,40.536) 173.964,40.536 175,39.5 175,34.5 174,33.5 174,30.649 ; v1@165.5,42.5 165.5,48.649 ; VD_62.2@172.5,30.7 172.5,30.623 172.623,30.5 173.851,30.5 174,30.649 ; v1(173.991,22.536) 173.991,6.399 174.14,6.25 281.101,6.25 281.25,6.399 281.25,29.75 283.992,32.492 283.992,37.03 284,37.037 284,44.25 285.5,45.75 D1.26@287.8,45.75 ; v1(174,24.5) 174,30.649
Col_9: D1.27 VD_9.2 VD_22.2 VD_36.2 VD_50.2 VD_63.2 VD_72.2 | length 291.3
  Top Layer w0.254: v1(170,76.5) v1(170,78.5) ; v1@170.5,94 v1(170.5,97.5) ; v1(179,58.5) v1(179,60.5) ; v1(183.491,42.536) 183.5,42.527 v1@183.5,40.5 ; v1(208.491,24.536) 208.5,24.527 v1@208.5,22.5
  Bottom Layer w0.254: VD_22.2@168,84.7 169.7,84.7 170,85 ; v1(170,76.5) 179,76.5 179.5,76 179.5,70.5 179,70 179,66.649 ; v1(170,78.5) 170,85 ; v1(170.5,97.5) 171.5,98.5 189.5,98.5 191.5,100.5 191.5,110.2 193.702,112.402 193.877,112.402 194,112.525 VD_9.2@194,112.7 ; v1(170.507,94.002) 170.5,93.995 170.5,89 170,88.5 170,85 ; VD_36.2@177,66.7 177,66.623 177.123,66.5 178.851,66.5 179,66.649 ; v1(179,58.5) 183.5,58.5 184,58 184,52.5 183.5,52 183.5,48.5 ; v1(179,60.5) 179,66.649 ; VD_50.2@181.5,48.7 183.3,48.7 183.5,48.5 ; v1(183.491,40.536) 191.964,40.536 193,39.5 193,34.5 192,33.5 192,30.649 ; v1@183.5,42.5 183.5,48.5 ; VD_63.2@190.5,30.7 190.5,30.623 190.623,30.5 191.851,30.5 192,30.649 ; v1(208.491,22.536) 209.964,22.536 211,21.5 211,12.649 210.851,12.5 ; VD_72.2@208.5,12.7 208.5,12.623 208.623,12.5 210.851,12.5 ; v1@208.5,24.5 207.5,25.5 193,25.5 192,26.5 192,30.649 ; D1.27@287.8,46.25 285,46.25 283.25,44.5 283.25,38.037 283.242,38.03 283.242,32.742 280.5,30 280.5,7.149 280.351,7 211,7 210.851,7.149 210.851,12.5
Col_10: D1.28 VD_10.2 VD_23.2 VD_37.2 VD_51.2 VD_64.2 VD_73.2 | length 284.4
  Top Layer w0.254: v1(187.5,76.5) v1(187.5,78.5) ; v1(197,58.5) v1(197,60.5) ; v1(201.491,42.536) 201.5,42.527 v1@201.5,40.5 ; v1@204,94.5 v1(204,103.5) ; v1(233.491,24.536) 233.5,24.527 v1@233.5,22.5
  Bottom Layer w0.254: VD_23.2@186,84.7 187.351,84.7 187.5,84.849 ; v1(187.5,76.5) 197,76.5 197.5,76 197.5,70.5 197,70 197,66.649 ; v1(187.5,78.5) 187.5,84.849 ; VD_37.2@195,66.7 195,66.623 195.123,66.5 196.851,66.5 197,66.649 ; v1(197,58.5) 201,58.5 202,57.5 202,52.5 201.5,52 201.5,48.649 ; v1(197,60.5) 197,66.649 ; VD_51.2@199.5,48.7 199.5,48.623 199.623,48.5 201.351,48.5 201.5,48.649 ; v1(201.491,40.536) 201.527,40.5 210,40.5 211,39.5 211,34.5 210,33.5 210,30.649 209.851,30.5 ; v1@201.5,42.5 201.5,48.649 ; v1(203.933,94.547) 203.886,94.5 200,94.5 196,90.5 190,90.5 187.5,88 187.5,84.849 ; v1(204,103.5) 204.5,104 223,104 224,105 VD_10.2@224,112.7 ; VD_64.2@208.5,30.7 208.5,30.623 208.623,30.5 209.851,30.5 ; VD_73.2@230.5,12.7 230.5,12.623 230.623,12.5 233.351,12.5 233.5,12.649 ; v1(233.491,22.536) 233.5,22.527 233.5,12.649 ; v1@233.5,24.5 232.5,25.5 210.5,25.5 209.851,26.149 209.851,30.5 ; D1.28@287.8,46.75 284.5,46.75 282.5,44.75 282.5,37.037 282.492,37.03 282.492,32.992 279.75,30.25 279.75,7.899 279.601,7.75 233.649,7.75 233.5,7.899 233.5,12.649
Col_11: D1.29 VD_11.2 VD_24.2 VD_38.2 VD_52.2 VD_65.2 VD_74.2 | length 266.2
  Top Layer w0.254: v1(206,76.5) v1(206,78.5) ; v1(206.5,94.5) v1(206.5,103) ; v1(215,58.5) v1(215,60.5) ; v1(219.491,42.536) 219.5,42.527 v1@219.5,40.5 ; v1(255.491,24.536) 255.5,24.527 v1@255.5,22.5
  Bottom Layer w0.254: VD_24.2@204,84.7 205.8,84.7 206,84.9 ; v1(206,76.5) 215,76.5 215.5,76 215.5,70.5 215,70 215,66.649 ; v1(206,78.5) 206,84.9 ; v1(206.5,94.5) 206.5,89 206,88.5 206,84.9 ; v1(206.5,103) 223,103 224,104 241,104 242,105 VD_11.2@242,112.7 ; VD_38.2@213,66.7 213,66.623 213.123,66.5 214.851,66.5 215,66.649 ; v1(215,58.5) 219.5,58.5 220,58 220,52.5 219.5,52 219.5,48.649 ; v1(215,60.5) 215,66.649 ; VD_52.2@217.5,48.7 217.5,48.623 217.623,48.5 219.351,48.5 219.5,48.649 ; v1(219.491,40.536) 219.527,40.5 228,40.5 229,39.5 229,30.649 ; v1@219.5,42.5 219.5,48.649 ; VD_65.2@226.5,30.7 226.5,30.623 226.623,30.5 228.851,30.5 229,30.649 ; VD_74.2@253.5,12.7 253.5,12.623 253.623,12.5 255.351,12.5 255.5,12.649 ; v1(255.491,22.536) 255.5,22.527 255.5,12.649 ; v1@255.5,24.5 254.5,25.5 234.5,25.5 233.5,26.5 230,26.5 229,27.5 229,30.649 ; D1.29@287.8,47.25 284,47.25 281.75,45 281.75,38.037 281.742,38.03 281.742,33.242 279,30.5 279,8.649 278.851,8.5 255.649,8.5 255.5,8.649 255.5,12.649
Col_12: D1.30 VD_12.2 VD_25.2 VD_39.2 VD_53.2 VD_66.2 VD_75.2 | length 227.5
  Top Layer w0.254: v1(224,76.5) v1(224,78.5) ; v1@224.5,94.5 v1(224.5,103) ; v1(233,58.5) v1(233,60.5) ; v1@238,40.5 238,42.493 v1(238.005,42.498) ; v1(262.25,24.75) 269.25,24.75 269.5,24.5 269.5,23.25 270.25,22.5 v1(272.25,22.5)
  Bottom Layer w0.254: VD_25.2@222,84.7 223.7,84.7 224,85 ; v1(224,76.5) 233,76.5 233.5,76 233.5,70.5 233,70 233,66.649 ; v1(224,78.5) 224,85 ; v1(224.477,94.529) 224.5,94.506 224.5,89 224,88.5 224,85 ; v1(224.5,103) 258.5,103 260,104.5 VD_12.2@260,112.7 ; VD_39.2@231,66.7 231,66.623 231.123,66.5 232.851,66.5 233,66.649 ; v1(233,58.5) 237,58.5 238,57.5 238,48.649 ; v1(233,60.5) 233,66.649 ; VD_53.2@235.5,48.7 235.5,48.623 235.623,48.5 237.851,48.5 238,48.649 ; v1@238,42.5 238,48.649 ; v1(238.005,40.498) 238.005,36.995 238.5,36.5 253.5,36.5 256,34 256,32 257.3,30.7 262.101,30.7 262.25,30.551 v1(262.25,24.75) ; v1(272.25,22.5) 278.25,22.5 ; VD_75.2@275.5,12.7 275.5,12.623 275.623,12.5 278.101,12.5 278.25,12.649 278.25,22.5 ; D1.30@287.8,47.75 283.5,47.75 281,45.25 281,37.037 280.992,37.03 280.992,33.492 278.25,30.75 278.25,22.5
Col_13: D1.31 VD_13.2 VD_26.2 VD_27.2 VD_40.2 VD_41.2 VD_54.2 | length 167.2
  Top Layer w0.254: v1(270,96.5) 270,97.5 v1(275.5,103) ; v1(275.492,48.78) 277.022,47.25 v1(280.75,47.25)
  Bottom Layer w0.254: VD_26.2@240,84.7 240,84.623 240.123,84.5 243.5,84.5 ; VD_40.2@249,66.7 248.149,66.7 247.5,67.349 247.5,69.5 246.5,70.5 243,70.5 242.5,71 242.5,74 243.5,75 243.5,84.5 ; VD_54.2@266,48.7 275.7,48.7 276,49 276,66.649 ; VD_27.2@267,85 269.5,85 ; VD_41.2@272.5,66.7 272.5,66.623 272.623,66.5 275.851,66.5 276,66.649 ; v1(275.5,103) 278,105.5 VD_13.2@278,112.7 ; v1(280.75,47.25) 282,47.25 283,48.25 D1.31@287.8,48.25 ; 243.5,84.5 243.5,94 246,96.5 v1(270,96.5) 270,85.5 ; 269.5,85 270,85.5 ; 269.5,85 269.851,85 ; 269.851,85 274.5,85 276,83.5 276,66.649 ; 269.851,85 270,85.149 270,85.5
Col_14: D1.45 VD_76.2 VD_83.2 VD_90.2 VD_105.2 | length 198.8
  Top Layer w0.254: v1@308,22.5 v1(308,25.5) ; v1(308,76.5) v1(308,78.5) ; v1(308.479,97.013) 308.5,96.992 v1(308.5,94)
  Bottom Layer w0.254: D1.45@293.25,52.2 293.25,57.25 294,58 310.25,58 315.25,53 332.5,53 ; VD_105.2@306,12.7 306,12.623 306.123,12.5 307.851,12.5 308,12.649 308,16 308.5,16.5 308.5,22 308.005,22.495 v1(308.005,22.498) ; VD_90.2@306,66.7 306,66.623 306.123,66.5 307.851,66.5 308,66.649 ; VD_83.2@306,84.7 307.7,84.7 308,85 ; VD_76.2@306,112.7 306,112.525 308.025,110.5 308.025,110.475 308.5,110 v1@308.5,97 ; v1(308,25.5) 308,41.5 309,42.5 332,42.5 332.5,43 332.5,53 ; v1(308,76.5) 308.5,76 308.5,70.5 308,70 308,66.649 ; v1(308,78.5) 308,85 ; v1(308.5,94) 308.5,88.5 308,88 308,85 ; 308,66.649 308,65.5 315,58.5 331.5,58.5 332.5,57.5 332.5,53
Col_15: D1.46 VD_77.2 VD_84.2 VD_91.2 VD_100.2 VD_106.2 | length 175.6
  Top Layer w0.254: v1(326,76.5) v1(326,78.5) ; v1@326.5,22.5 326.5,24.493 v1(326.505,24.498) ; v1(326.5,94) v1(326.5,97) ; v1(331.31,52.009) 331.318,52 v1@333.5,52 ; v1@333.5,40.5 333.5,42.493 v1(333.505,42.498)
  Bottom Layer w0.254: D1.46@293.75,52.2 293.75,56.75 294.25,57.25 310,57.25 315.25,52 v1@331.357,52 ; VD_106.2@324,12.7 324,12.623 324.123,12.5 325.851,12.5 326,12.649 326,16 326.505,16.505 v1(326.505,22.498) ; VD_100.2@324,30.7 324,30.623 324.123,30.5 326,30.5 326.505,29.995 326.505,25.351 ; VD_91.2@324,66.7 324,66.623 324.123,66.5 325.851,66.5 326,66.649 ; VD_84.2@324,84.7 325.7,84.7 326,85 ; VD_77.2@324,112.7 324,112.525 326.5,110.025 v1(326.5,97) ; v1(326,76.5) 326.5,76 326.5,70.5 326,70 326,66.649 ; v1(326,78.5) 326,85 ; v1(326.5,94) 326.5,88.5 326,88 326,85 ; v1(326.505,24.498) 326.505,25.351 ; v1@333.5,42.5 333.5,58 332.25,59.25 326.5,59.25 326,59.75 326,66.649 ; v1(333.505,40.498) 333.5,40.493 333.5,26.25 332.75,25.5 326.653,25.5 326.505,25.351
  other v1: 333.503,51.983
Col_16: D1.10 VD_78.2 VD_85.2 VD_92.2 VD_107.2 | length 242.2
  Top Layer w0.254: v1(299,41.75) 306.928,41.75 307.178,41.5 v1(307.25,41.5) ; v1(344.5,22.5) v1(344.5,24.5) ; v1@344.5,40.5 344.5,42.493 v1(344.505,42.498) ; v1(344.5,76.5) v1(344.5,78.5) ; v1(344.5,94) v1(344.5,97)
  Bottom Layer w0.254: D1.10@296.2,46.25 297.386,46.25 298.289,45.347 298.289,41.833 298.438,41.684 298.934,41.684 v1(299,41.75) ; v1(307.25,41.5) 307.25,24.75 307,24.5 290.75,24.5 290.25,24 290.25,4.25 290.5,4 344.851,4 345,4.149 345,12.649 ; VD_107.2@342,12.7 342,12.623 342.123,12.5 344.851,12.5 345,12.649 ; VD_92.2@342,66.7 342,66.623 342.123,66.5 344.351,66.5 344.5,66.649 ; VD_85.2@342,84.7 342,84.623 342.123,84.5 344.351,84.5 344.5,84.649 ; VD_78.2@342,112.7 342,112.525 344.5,110.025 v1(344.5,97) ; v1(344.5,22.5) 344.5,22.002 345,21.502 345,12.649 ; v1(344.5,24.5) 344.5,40.493 v1(344.505,40.498) ; v1@344.5,42.5 344.5,66.649 ; v1(344.5,76.5) 344.5,66.649 ; v1(344.5,78.5) 344.5,84.649 ; v1(344.5,94) 344.5,84.649
Col_17: D1.12 VD_79.2 VD_86.2 VD_93.2 VD_97.2 VD_101.2 VD_108.2 | length 273.6
  Top Layer w0.254: v1@372,22.5 372,24.493 v1(372.005,24.498) ; v1@372,40.5 372,42.493 v1(372.005,42.498) ; v1@372,58.5 372,60.493 v1(372.005,60.498) ; v1@372,76.5 372,78.668 v1(372.003,78.67) ; v1(372.5,94) v1(372.5,97)
  Bottom Layer w0.254: D1.12@296.2,45.25 297,45.25 297.25,45 297.25,43.5 296.75,43 295.75,43 295.25,42.5 295.25,34.25 294.75,33.75 293.25,33.75 292.25,32.75 292.25,29.75 289.5,27 289.5,3.399 289.649,3.25 381.75,3.25 382,3.5 382,12.649 ; VD_101.2@370,30.7 370,30.623 370.123,30.5 371.851,30.5 372,30.649 ; VD_97.2@370,48.7 371.851,48.7 372,48.849 ; VD_93.2@370,66.7 370,66.623 370.123,66.5 371.851,66.5 372,66.649 ; VD_86.2@370,84.7 370,84.623 370.123,84.5 371.851,84.5 372,84.649 ; VD_79.2@370,112.7 370,112.525 372.025,110.5 372.351,110.5 372.5,110.351 v1(372.5,97) ; v1@372,24.5 372,30.649 ; v1@372,42.5 372,48.849 ; v1@372,60.5 372,66.649 ; v1@372,78.5 372,84.649 ; v1(372.005,40.498) 372.005,40.495 372.5,40 372.5,34.5 372,34 372,30.649 ; v1(372.005,58.498) 372.5,58.002 372.5,52.5 372,52 372,48.849 ; v1(372.016,76.501) 372.016,76.484 372.5,76 372.5,70.5 372,70 372,66.649 ; v1(372.048,22.525) 381.475,22.525 382,22 382,12.649 ; v1(372.5,94) 372.5,88.5 372,88 372,84.649 ; VD_108.2@379,12.7 379,12.623 379.123,12.5 381.851,12.5 382,12.649
Col_18: D1.13 VD_80.2 VD_87.2 VD_94.2 VD_98.2 VD_102.2 | length 267.3
  Top Layer w0.254: v1(389.995,60.493) 390,60.487 v1(390,58.5) ; v1(390,22.5) v1(390,24.5) ; v1@390,40.5 390,42.568 v1(390.02,42.588) ; v1(390,76.5) v1(390,78.5) ; v1(390.5,94) v1(390.5,97)
  Bottom Layer w0.254: D1.13@294.75,43.8 294.75,34.75 294.25,34.25 292.5,34.25 291.5,33.25 291.5,30 288.75,27.25 288.75,2.649 288.899,2.5 389.75,2.5 390,2.75 v1(390,22.5) ; VD_102.2@388,30.7 388,30.623 388.123,30.5 389.851,30.5 390,30.649 ; VD_98.2@388,48.7 388,48.623 388.123,48.5 389.851,48.5 390,48.649 ; VD_94.2@388,66.7 388,66.623 388.123,66.5 389.851,66.5 390,66.649 ; VD_87.2@388,84.7 389.851,84.7 390,84.849 ; VD_80.2@388,112.7 388,112.525 390.5,110.025 v1(390.5,97) ; v1(390,24.5) 390,30.649 ; v1@390,42.5 390,48.649 ; v1(390,58.5) 390.5,58 390.5,52.5 390,52 390,48.649 ; v1@390,60.5 390,66.649 ; v1(390,76.5) 390.5,76 390.5,70.5 390,70 390,66.649 ; v1(390,78.5) 390,84.849 ; v1(390.02,40.588) 390.02,40.585 390.5,40.105 390.5,34.5 390,34 390,30.649 ; v1(390.5,94) 390.5,89 390,88.5 390,84.849
Col_19: D1.14 VD_81.2 VD_88.2 VD_95.2 VD_99.2 VD_103.2 VD_109.2 | length 291.7
  Top Layer w0.254: v1(408,76.5) v1(408,78.5) ; v1(408.5,40.5) v1(408.5,42.5) ; v1@408.5,94 v1(408.5,97)
  Bottom Layer w0.254: D1.14@294.25,43.8 294.25,35.25 293.75,34.75 291.75,34.75 290.75,33.75 290.75,30.25 288,27.5 288,1.899 288.149,1.75 407.75,1.75 408.351,2.351 408.351,12.5 ; VD_109.2@406,12.7 406,12.623 406.123,12.5 408.351,12.5 ; VD_103.2@406,30.7 406,30.623 406.123,30.5 408.351,30.5 408.5,30.649 ; VD_99.2@406,48.7 406,48.623 406.123,48.5 408.351,48.5 408.5,48.649 ; VD_95.2@406,66.7 406,66.623 406.123,66.5 408.351,66.5 408.5,66.649 ; VD_88.2@406,84.7 406,84.623 406.123,84.5 407.851,84.5 408,84.649 ; VD_81.2@406,112.7 406,112.525 408.5,110.025 v1(408.5,97) ; v1(408,76.5) 408.5,76 408.5,66.649 ; v1(408,78.5) 408,84.649 ; v1(408.485,93.948) 408.485,88.485 408,88 408,84.649 ; v1(408.5,40.5) 408.5,30.649 ; v1(408.5,42.5) 408.5,48.649 ; 408.351,12.5 408.5,12.649 408.5,22 408,22.5 408,25.5 408.5,26 408.5,30.649 ; 408.5,48.649 408.5,58 408,58.5 408,61 408.5,61.5 408.5,66.649
Col_20: D1.15 VD_82.2 VD_89.2 VD_96.2 VD_104.2 | length 303.3
  Bottom Layer w0.254: D1.15@293.75,43.8 293.75,35.75 293.25,35.25 291,35.25 290,34.25 290,30.5 287.25,27.75 287.25,1.149 287.399,1 421,1 426.426,6.426 426.426,21.676 ; VD_104.2@424,21.7 424,21.623 424.123,21.5 426.25,21.5 426.426,21.676 ; VD_96.2@424,57.7 424,57.623 424.123,57.5 426.277,57.5 426.426,57.649 ; VD_89.2@424,84.7 424,84.623 424.123,84.5 426.351,84.5 426.426,84.574 ; VD_82.2@424,112.7 424,112.525 426.5,110.025 426.5,84.649 426.426,84.574 ; 426.426,21.676 426.426,57.649 ; 426.426,57.649 426.426,84.574
DU_N: R4.1 X1.A7 X1.B7 | length 147
  Bottom Layer w0.254: X1.A7@200.65,124.1 200.65,125.55 200.5,125.7 199.799,125.7 199.65,125.551 X1.B7@199.65,124.1 199.65,122.475 199.976,122.149 199.976,104.099 200.45,103.625 203.1,100.975 278,100.975 280.057,98.918 280.057,59.8 280.057,58.857 R4.1@279.7,58.5
DU_P: R3.1 X1.A6 X1.B6 | length 145
  Bottom Layer w0.254: X1.A6@200.15,124.1 200.15,122.875 200.35,122.675 200.611,122.675 ; X1.B6@201.15,124.1 201.15,122.875 200.95,122.675 200.611,122.675 ; R3.1@281.1,58.5 280.692,58.908 280.692,59.8 280.692,99.181 278.263,101.61 203.363,101.61 200.611,104.362 200.611,122.675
